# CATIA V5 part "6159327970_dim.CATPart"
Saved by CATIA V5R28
Part number: 6159327970_dim
Source: made
Property "PROI_CREATED_ON": "12/17/2008 9:21:37 AM"
Property "BLANK_DRAWING": "--"
Property "DRAWN_BY": "FPA"
Property "FINISH": "--"
Property "HEAT_TREATMENT": "ASSIGN"
Property "MATERIAL": "ASSIGN"
Property "PROJECT": "--"
Property "PROTOTYPE_NO": "--"
Property "RELATED_DRAWING": "--"
Property "COMPLETE_MATERIAL": "ASSIGN-ASSIGN"
Property "DESCRIPTION": "AXD + AXM-SX Essential"
Property "DRAWING_EXIST": "--"
Property "MANUFACTURER": "--"
Property "MANUFACTURER_2": "--"
Property "MANUFACTURER_REF": "--"
Property "TYPE_PART": "--"
Property "TODAY_DATE": "2026/03/23"
Property "PDMREV": "01.0"
Property "PDMRL": "Production"
Property "PROI_REVISION": "01"
Property "PROI_VERSION": "0"
Property "PROI_RELEASE": "Production"
Property "PTC_MODIFIED": false
Property "MFG_WP_MATERIAL": "ASSIGN"
Property "COMPANY_CODE": "---"
Property "DESCRIPTION_JP": "--"
Property "PQP_DOCUMENT": "--"
Property "GHOST": false
Property "NO_PART": false
Property "REFERENCE": "6159327950_DIM"
Property "PTC_WM_ITERATION": "0"
Property "PTC_WM_VERSION": "01.0"
Property "PTC_WM_CREATED_ON": "24-Mar-26 09:23:24 AM"
Property "PTC_WM_MODIFIED_ON": "24-Mar-26 09:23:24 AM"
Property "PTC_WM_NAME": "6159327970_dim.prt"
Property "PTC_WM_NUMBER": "6159327970_DIM.PRT"
Property "PTC_WM_LIFECYCLE_STATE": "Production"
Property "PTC_WM_LIFECYCLE": "Design_Process"
Property "PTC_WM_REVISION": "01"
Property "PTC_WM_CREATED_BY": "Florian Pavageau (Grefpav) (Grefpav: CPD)"
Property "PTC_WM_MODIFIED_BY": "Florian Pavageau (Grefpav) (Grefpav: CPD)"
Property "PTC_ORGANIZATION_ID": "CPD"
Property "PTC_WM_TEAM": "Default"
Property "PTC_WM_LOCATION": "/Products/CONTROLLERS/A1770 - CX4 - SMART DRIVE - LEAN/9-01-Dimensional Drawings"
Property "PTC_WM_PART_NAME": "6159327970_dim"
Property "PTC_WM_PART_NUMBER": "6159327970_DIM"
Property "PTC_COMMON_NAME": "6159327970_dim.prt"
Property "PTC_MASTER_MATERIAL": "ASSIGN"
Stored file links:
  d:\ptc\Echange\temp\6159327970_dim.CATPart

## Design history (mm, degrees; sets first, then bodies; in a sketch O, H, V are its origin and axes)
AxisSystem1 "CS0": origin (0, 0, 0), X (1, 0, 0), Y (0, 1, 0), Z (0, 0, 1)
Set1
  DatumSurface1 "Sheet.1"
  DatumSurface2 "Sheet.2"
  DatumSurface3 "Sheet.3"
  DatumSurface4 "Sheet.4"
  DatumSurface5 "Sheet.5"
  DatumSurface6 "Sheet.6"
  DatumSurface7 "Sheet.7"
  DatumSurface8 "Sheet.8"
  DatumSurface9 "Sheet.9"
  DatumSurface10 "Sheet.10"
  DatumSurface11 "Sheet.11"
  DatumSurface12 "Sheet.12"
  DatumSurface13 "Sheet.13"
  DatumSurface14 "Sheet.14"
  DatumSurface15 "Sheet.15"
  DatumSurface16 "Sheet.16"
  DatumSurface17 "Sheet.17"
  DatumSurface18 "Sheet.18"
  DatumSurface19 "Sheet.19"
  DatumSurface20 "Sheet.20"
  DatumSurface21 "Sheet.21"
  DatumSurface22 "Sheet.22"
  DatumSurface23 "Sheet.23"
  DatumSurface24 "Sheet.24"
  DatumSurface25 "Sheet.25"
  DatumSurface26 "Sheet.26"
  DatumSurface27 "Sheet.27"
  DatumSurface28 "Sheet.28"
  DatumSurface29 "Sheet.29"
  DatumSurface30 "Sheet.30"
  DatumSurface31 "Sheet.31"
  DatumSurface32 "Sheet.32"
  DatumSurface33 "Sheet.33"
  DatumSurface34 "Sheet.34"
  DatumSurface35 "Sheet.35"
  DatumSurface36 "Sheet.36"
  DatumSurface37 "Sheet.37"
  DatumSurface38 "Sheet.38"
  DatumSurface39 "Sheet.39"
  DatumSurface40 "Sheet.40"
  DatumSurface41 "Sheet.41"
  DatumSurface42 "Sheet.42"
  DatumSurface43 "Sheet.43"
  DatumSurface44 "Sheet.44"
  DatumSurface45 "Sheet.45"
  DatumSurface46 "Sheet.46"
  DatumSurface47 "Sheet.47"
  DatumSurface48 "Sheet.48"
  DatumSurface49 "Sheet.49"
  DatumSurface50 "Sheet.50"
  DatumSurface51 "Sheet.51"
  DatumSurface52 "Sheet.52"
  DatumSurface53 "Sheet.53"
  DatumSurface54 "Sheet.54"
  DatumSurface55 "Sheet.55"
  DatumSurface56 "Sheet.56"
  DatumSurface57 "Sheet.57"
  DatumSurface58 "Sheet.58"
  DatumSurface59 "Sheet.59"
  DatumSurface60 "Sheet.60"
  DatumSurface61 "Sheet.61"
  DatumSurface62 "Sheet.62"
  DatumSurface63 "Sheet.63"
  DatumSurface64 "Sheet.64"
  DatumSurface65 "Sheet.65"
  DatumSurface66 "Sheet.66"
  DatumSurface67 "Sheet.67"
  DatumSurface68 "Sheet.68"
  DatumSurface69 "Sheet.69"
  DatumSurface70 "Sheet.70"
  DatumSurface71 "Sheet.71"
  DatumSurface72 "Sheet.72"
  DatumSurface73 "Sheet.73"
  DatumSurface74 "Sheet.74"
  DatumSurface75 "Sheet.75"
  DatumSurface76 "Sheet.76"
  DatumSurface77 "Sheet.77"
  DatumSurface78 "Sheet.78"
  DatumSurface79 "Sheet.79"
  DatumSurface80 "Sheet.80"
  DatumSurface81 "Sheet.81"
  DatumSurface82 "Sheet.82"
  DatumSurface83 "Sheet.83"
  DatumSurface84 "Sheet.84"
  DatumSurface85 "Sheet.85"
  DatumSurface86 "Sheet.86"
  DatumSurface87 "Sheet.87"
  DatumSurface88 "Sheet.88"
  DatumSurface89 "Sheet.89"
  DatumSurface90 "Sheet.90"
  DatumSurface91 "Sheet.91"
  DatumSurface92 "Sheet.92"
  DatumSurface93 "Sheet.93"
  DatumSurface94 "Sheet.94"
  DatumSurface95 "Sheet.95"
  DatumSurface96 "Sheet.96"
  DatumSurface97 "Sheet.97"
  DatumSurface98 "Sheet.98"
  DatumSurface99 "Sheet.99"
  DatumSurface100 "Sheet.100"
  DatumSurface101 "Sheet.101"
  DatumSurface102 "Sheet.102"
  DatumSurface103 "Sheet.103"
  DatumSurface104 "Sheet.104"
  DatumSurface105 "Sheet.105"
  DatumSurface106 "Sheet.106"
  DatumSurface107 "Sheet.107"
  DatumSurface108 "Sheet.108"
  DatumSurface109 "Sheet.109"
  DatumSurface110 "Sheet.110"
  DatumSurface111 "Sheet.111"
  DatumSurface112 "Sheet.112"
  DatumSurface113 "Sheet.113"
  DatumSurface114 "Sheet.114"
  DatumSurface115 "Sheet.115"
  DatumSurface116 "Sheet.116"
  DatumSurface117 "Sheet.117"
  DatumSurface118 "Sheet.118"
  DatumSurface119 "Sheet.119"
  DatumSurface120 "Sheet.120"
  DatumSurface121 "Sheet.121"
  DatumSurface122 "Sheet.122"
  DatumSurface123 "Sheet.123"
  DatumSurface124 "Sheet.124"
  DatumSurface125 "Sheet.125"
  DatumSurface126 "Sheet.126"
  DatumSurface127 "Sheet.127"
  DatumSurface128 "Sheet.128"
  DatumSurface129 "Sheet.129"
  DatumSurface130 "Sheet.130"
  DatumSurface131 "Sheet.131"
  DatumSurface132 "Sheet.132"
  DatumSurface133 "Sheet.133"
  DatumSurface134 "Sheet.134"
  DatumSurface135 "Sheet.135"
  DatumSurface136 "Sheet.136"
  DatumSurface137 "Sheet.137"
  DatumSurface138 "Sheet.138"
  DatumSurface139 "Sheet.139"
  DatumSurface140 "Sheet.140"
  DatumSurface141 "Sheet.141"
  DatumSurface142 "Sheet.142"
  DatumSurface143 "Sheet.143"
  DatumSurface144 "Sheet.144"
  DatumSurface145 "Sheet.145"
  DatumSurface146 "Sheet.146"
  DatumSurface147 "Sheet.147"
  DatumSurface148 "Sheet.148"
  DatumSurface149 "Sheet.149"
  DatumSurface150 "Sheet.150"
  DatumSurface151 "Sheet.151"
  DatumSurface152 "Sheet.152"
  DatumSurface153 "Sheet.153"
  DatumSurface154 "Sheet.154"
  DatumSurface155 "Sheet.155"
  DatumSurface156 "Sheet.156"
  DatumSurface157 "Sheet.157"
  DatumSurface158 "Sheet.158"
  DatumSurface159 "Sheet.159"
  DatumSurface160 "Sheet.160"
  DatumSurface161 "Sheet.161"
  DatumSurface162 "Sheet.162"
  DatumSurface163 "Sheet.163"
  DatumSurface164 "Sheet.164"
  DatumSurface165 "Sheet.165"
  DatumSurface166 "Sheet.166"
  DatumSurface167 "Sheet.167"
  DatumSurface168 "Sheet.168"
  DatumSurface169 "Sheet.169"
  DatumSurface170 "Sheet.170"
  DatumSurface171 "Sheet.171"
  DatumSurface172 "Sheet.172"
  DatumSurface173 "Sheet.173"
  DatumSurface174 "Sheet.174"
  DatumSurface175 "Sheet.175"
  DatumSurface176 "Sheet.176"
  DatumSurface177 "Sheet.177"
  DatumSurface178 "Sheet.178"
  DatumSurface179 "Sheet.179"
  DatumSurface180 "Sheet.180"
  DatumSurface181 "Sheet.181"
  DatumSurface182 "Sheet.182"
  DatumSurface183 "Sheet.183"
  DatumSurface184 "Sheet.184"
  DatumSurface185 "Sheet.185"
  DatumSurface186 "Sheet.186"
  DatumSurface187 "Sheet.187"
  DatumSurface188 "Sheet.188"
  DatumSurface189 "Sheet.189"
  DatumSurface190 "Sheet.190"
  DatumSurface191 "Sheet.191"
  DatumSurface192 "Sheet.192"
  DatumSurface193 "Sheet.193"
  DatumSurface194 "Sheet.194"
  DatumSurface195 "Sheet.195"
  DatumSurface196 "Sheet.196"
  DatumSurface197 "Sheet.197"
  DatumSurface198 "Sheet.198"
  DatumSurface199 "Sheet.199"
  DatumSurface200 "Sheet.200"
  DatumSurface201 "Sheet.201"
  DatumSurface202 "Sheet.202"
  DatumSurface203 "Sheet.203"
  DatumSurface204 "Sheet.204"
  DatumSurface205 "Sheet.205"
  DatumSurface206 "Sheet.206"
  DatumSurface207 "Sheet.207"
  DatumSurface208 "Sheet.208"
  DatumSurface209 "Sheet.209"
  DatumSurface210 "Sheet.210"
  DatumSurface211 "Sheet.211"
  DatumSurface212 "Sheet.212"
  DatumSurface213 "Sheet.213"
  DatumSurface214 "Sheet.214"
  DatumSurface215 "Sheet.215"
  DatumSurface216 "Sheet.216"
  DatumSurface217 "Sheet.217"
  DatumSurface218 "Sheet.218"
  DatumSurface219 "Sheet.219"
  DatumSurface220 "Sheet.220"
  DatumSurface221 "Sheet.221"
  DatumSurface222 "Sheet.222"
  DatumSurface223 "Sheet.223"
  DatumSurface224 "Sheet.224"
  DatumSurface225 "Sheet.225"
  DatumSurface226 "Sheet.226"
  DatumSurface227 "Sheet.227"
  DatumSurface228 "Sheet.228"
  DatumSurface229 "Sheet.229"
  DatumSurface230 "Sheet.230"
  DatumSurface231 "Sheet.231"
  DatumSurface232 "Sheet.232"
  DatumSurface233 "Sheet.233"
  DatumSurface234 "Sheet.234"
  DatumSurface235 "Sheet.235"
  DatumSurface236 "Sheet.236"
  DatumSurface237 "Sheet.237"
  DatumSurface238 "Sheet.238"
  DatumSurface239 "Sheet.239"
  DatumSurface240 "Sheet.240"
  DatumSurface241 "Sheet.241"
  DatumSurface242 "Sheet.242"
  DatumSurface243 "Sheet.243"
  DatumSurface244 "Sheet.244"
  DatumSurface245 "Sheet.245"
  DatumSurface246 "Sheet.246"
  DatumSurface247 "Sheet.247"
  DatumSurface248 "Sheet.248"
  DatumSurface249 "Sheet.249"
  DatumSurface250 "Sheet.250"
  DatumSurface251 "Sheet.251"
  DatumSurface252 "Sheet.252"
  DatumSurface253 "Sheet.253"
  DatumSurface254 "Sheet.254"
  DatumSurface255 "Sheet.255"
  DatumSurface256 "Sheet.256"
  DatumSurface257 "Sheet.257"
  DatumSurface258 "Sheet.258"
  DatumSurface259 "Sheet.259"
  DatumSurface260 "Sheet.260"
  DatumSurface261 "Sheet.261"
  DatumSurface262 "Sheet.262"
  DatumSurface263 "Sheet.263"
  DatumSurface264 "Sheet.264"
  DatumSurface265 "Sheet.265"
  DatumSurface266 "Sheet.266"
  DatumSurface267 "Sheet.267"
  DatumSurface268 "Sheet.268"
  DatumSurface269 "Sheet.269"
  DatumSurface270 "Sheet.270"
  DatumSurface271 "Sheet.271"
  DatumSurface272 "Sheet.272"
  DatumSurface273 "Sheet.273"
  DatumSurface274 "Sheet.274"
  DatumSurface275 "Sheet.275"
  DatumSurface276 "Sheet.276"
  DatumSurface277 "Sheet.277"
  DatumSurface278 "Sheet.278"
  DatumSurface279 "Sheet.279"
  DatumSurface280 "Sheet.280"
  DatumSurface281 "Sheet.281"
  DatumSurface282 "Sheet.282"
  DatumSurface283 "Sheet.283"
  DatumSurface284 "Sheet.284"
  DatumSurface285 "Sheet.285"
  DatumSurface286 "Sheet.286"
  DatumSurface287 "Sheet.287"
  DatumSurface288 "Sheet.288"
  DatumSurface289 "Sheet.289"
  DatumSurface290 "Sheet.290"
  DatumSurface291 "Sheet.291"
  DatumSurface292 "Sheet.292"
  DatumSurface293 "Sheet.293"
  DatumSurface294 "Sheet.294"
  DatumSurface295 "Sheet.295"
  DatumSurface296 "Sheet.296"
  DatumSurface297 "Sheet.297"
  DatumSurface298 "Sheet.298"
  DatumSurface299 "Sheet.299"
  DatumSurface300 "Sheet.300"
  DatumSurface301 "Sheet.301"
  DatumSurface302 "Sheet.302"
  Plane1 "RIGHT": stored without definition
  Plane2 "TOP": stored without definition
  Plane3 "FRONT": stored without definition
  Line1 "A_1": stored without definition
  Line2 "A_2": stored without definition
  Line3 "A_3": stored without definition
  Line4 "A_4": stored without definition
Body1 "PartBody" (main body)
